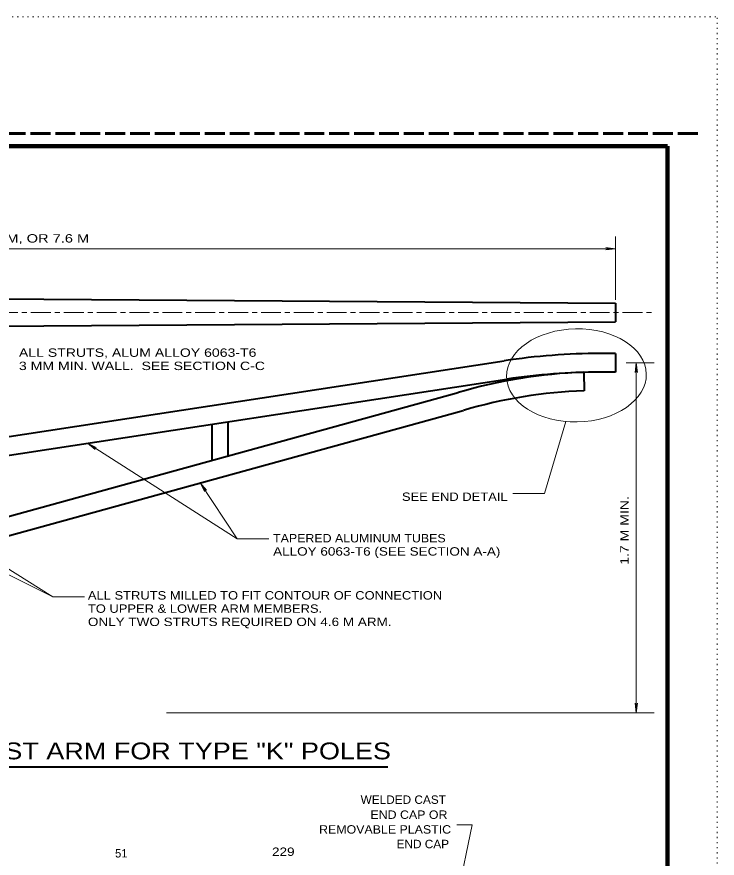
# Model space of a CAD drawing. Extents: x 312583 to 312854, y 144419 to 144597.
# Drawn here: x 312790.2 to 312853.5, y 144520.7 to 144596.8 of the extents above; entities that cross this region are included whole.
import ezdxf

# ---------------------------------------------------------------- set-up
doc = ezdxf.new("R2010")
doc.units = 0
doc.header["$LTSCALE"] = 0.3
for name, pattern in [('DOTTED', [1.5, 0.3, -1.2]), ('LONG_DASH_SHORT_DASH', [9.9, 6, -1.2, 1.5, -1.2]), ('LONG_DASHED', [7.5, 6, -1.5])]:
    doc.linetypes.add(name, pattern=pattern)
for name, color, linetype, lineweight in [('1', 7, 'Continuous', 13), ('62', 7, 'DOTTED', 13), ('63', 7, 'LONG_DASHED', 60)]:
    doc.layers.add(name, color=color, linetype=linetype, lineweight=lineweight)

msp = doc.modelspace()

# ---------------------------------------------------------------- linework, layer by layer
at = {"layer": '1'}
for p, q in [((312844.3174, 144571.1879), (312844.3174, 144576.9258)), ((312729.3174, 144575.826), (312844.3174, 144575.826)), ((312843.451, 144575.9333), (312843.727, 144575.826)), ((312844.3174, 144575.826), (312843.451, 144575.9333)), ((312843.451, 144575.7187), (312843.727, 144575.826)), ((312844.3174, 144575.826), (312843.451, 144575.7187)), ((312845.2757, 144565.5069), (312847.8219, 144565.5069)), ((312846.1905, 144565.5069), (312846.0832, 144564.6406)), ((312846.1905, 144565.5069), (312846.1905, 144533.8819)), ((312846.1905, 144565.5069), (312846.2978, 144564.6406)), ((312846.0832, 144564.6406), (312846.1905, 144564.9166)), ((312846.2978, 144564.6406), (312846.1905, 144564.9166)), ((312810.1164, 144549.5832), (312796.6077, 144558.2389)), ((312796.6077, 144558.2389), (312797.2824, 144557.6792)), ((312796.6077, 144558.2389), (312797.3974, 144557.8632)), ((312797.2824, 144557.6792), (312797.106, 144557.9169)), ((312797.3974, 144557.8632), (312797.106, 144557.9169)), ((312810.1164, 144549.5832), (312806.7814, 144554.6586)), ((312806.7814, 144554.6586), (312807.1647, 144553.8766)), ((312806.7814, 144554.6586), (312807.3487, 144553.9916)), ((312807.1647, 144553.8766), (312807.1034, 144554.1679)), ((312807.3487, 144553.9916), (312807.1034, 144554.1679)), ((312810.1164, 144549.5832), (312812.999, 144549.5832)), ((312793.4644, 144544.3469), (312796.3394, 144544.3469)), ((312846.0832, 144534.7482), (312846.1905, 144534.4722)), ((312846.1905, 144533.8819), (312846.0832, 144534.7482)), ((312846.2978, 144534.7482), (312846.1905, 144534.4722)), ((312846.1905, 144533.8819), (312846.2978, 144534.7482)), ((312803.7377, 144533.8819), (312847.8219, 144533.8819))]:
    msp.add_line(p, q, dxfattribs=at)
at = {"layer": '1', "lineweight": 40}
for p, q in [((312730.935, 144571.7246), (312844.3174, 144570.8966)), ((312844.3174, 144570.8966), (312844.3174, 144569.2252)), ((312730.935, 144568.3972), (312844.3174, 144569.2252)), ((312844.3174, 144566.3502), (312842.9374, 144566.3502)), ((312844.3174, 144566.3502), (312844.3174, 144564.6712)), ((312730.935, 144549.8976), (312834.251, 144565.6909)), ((312841.4424, 144564.6482), (312841.496, 144562.9769)), ((312844.3174, 144564.6712), (312842.9374, 144564.6712)), ((312730.935, 144548.1956), (312834.504, 144564.0272)), ((312730.935, 144535.5226), (312830.111, 144562.8236)), ((312730.9427, 144533.7822), (312830.5557, 144561.2059)), ((312807.8394, 144559.9562), (312807.8394, 144556.6902)), ((312809.2807, 144560.1709), (312809.2807, 144557.0889)), ((312764.502, 144528.9796), (312823.7493, 144528.9796))]:
    msp.add_line(p, q, dxfattribs=at)
at = {"layer": '1', "linetype": 'LONG_DASH_SHORT_DASH'}
msp.add_line((312726.151, 144570.0609), (312847.8219, 144570.0609), dxfattribs=at)
at = {"layer": '1', "lineweight": 158}
for points in [[(312616.5, 144423.0846), (312849, 144423.0846), (312849, 144585.0846)], [(312616.5, 144423.1446), (312616.5, 144585.0846), (312849, 144585.0846)]]:
    msp.add_lwpolyline(points, dxfattribs=at)
at = {"layer": '1'}
for points in [[(312835.0254, 144553.6926), (312837.9004, 144553.6926), (312839.84, 144560.2016)], [(312781.9644, 144556.0002), (312780.063, 144552.7726), (312793.4644, 144544.3469), (312782.7464, 144549.7136)], [(312828.7616, 144511.2116), (312831.3759, 144523.7542), (312829.9806, 144523.7542)]]:
    msp.add_lwpolyline(points, dxfattribs=at)
at = {"layer": '1', "lineweight": 40}
for centre, radius, start, end in [((312842.937, 144508.8474), 57.5, 90, 98.69133), ((312842.8932, 144519.6628), 45.0108, 91.84829, 106.4991), ((312842.937, 144508.8474), 55.8229, 90, 98.69133), ((312842.8932, 144519.6628), 43.3337, 91.84829, 106.4991)]:
    msp.add_arc(centre, radius, start, end, dxfattribs=at)
at = {"layer": '1'}
msp.add_ellipse((312840.782, 144564.3723), major_axis=(-6.3127, -0.1234), ratio=0.666667, dxfattribs=at)
at = {"layer": '62'}
msp.add_line((312601.2, 144596.7846), (312853.5, 144596.7846), dxfattribs=at)
msp.add_lwpolyline([(312601.2, 144418.5846), (312853.5, 144418.5846), (312853.5, 144596.7846)], dxfattribs=at)
at = {"layer": '63'}
msp.add_line((312851.75, 144586.2246), (312583.526, 144586.2246), dxfattribs=at)

# ---------------------------------------------------------------- texts
at = {"layer": '1'}
for s, height, width, p in [('4.6 M, 6.1 M, OR 7.6 M', 0.76, 1.3, (312783.0273, 144576.3771)), ('ALL STRUTS, ALUM ALLOY 6063-T6', 0.76, 1.25, (312790.4054, 144566.0502)), ('3 MM MIN. WALL.  SEE SECTION C-C', 0.76, 1.25, (312790.4054, 144564.8532)), ('SEE END DETAIL', 0.76, 1.15, (312825.017, 144553.0246)), ('TAPERED ALUMINUM TUBES', 0.76, 1.1, (312813.3747, 144549.2756)), ('ALLOY 6063-T6 (SEE SECTION A-A)', 0.76, 1.2, (312813.3747, 144548.0786)), ('ALL STRUTS MILLED TO FIT CONTOUR OF CONNECTION', 0.76, 1.15, (312796.6384, 144544.1082)), ('TO UPPER & LOWER ARM MEMBERS.', 0.76, 1.15, (312796.6384, 144542.9112)), ('ONLY TWO STRUTS REQUIRED ON 4.6 M ARM.', 0.76, 1.2, (312796.6384, 144541.7142)), ('TRAFFIC SIGNAL MAST ARM FOR TYPE "K" POLES', 1.52, 1.2, (312764.8291, 144529.6655)), ('WELDED CAST', 0.76, 1.05, (312821.2827, 144525.6407)), ('END CAP OR', 0.76, 1.1, (312822.1694, 144524.2837)), ('REMOVABLE PLASTIC', 0.76, 1.1, (312817.5286, 144522.9497)), ('229 ', 0.76, 1.2, (312813.2761, 144520.9339)), ('END CAP', 0.76, 1.05, (312824.5311, 144521.631))]:
    msp.add_text(s, height=height, dxfattribs=dict(at, width=width)).set_placement(p)
at = {"layer": '1', "width": 1.25}
msp.add_text('1.7 M MIN.', height=0.76, rotation=90, dxfattribs=at).set_placement((312845.4983, 144547.2456))
at = {"layer": '1'}
msp.add_text('51 ', height=0.76, dxfattribs=at).set_placement((312799.0935, 144520.792))

doc.saveas('drawing.dxf')
